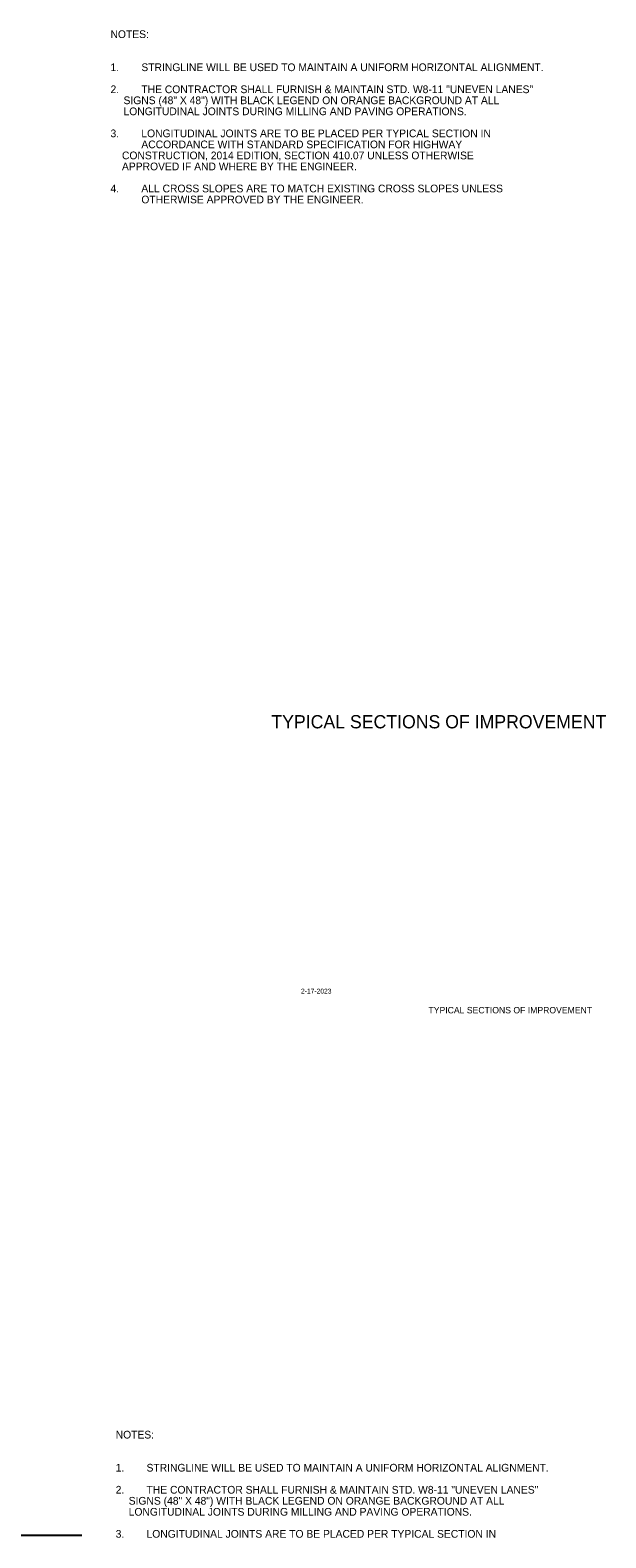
# Model space of a CAD drawing. Extents: x 549600 to 1930787, y -1955432 to 596640.
# Drawn here: x 552023 to 552546, y -1949917 to -1948549 of the extents above; entities that cross this region are included whole.
import ezdxf

# ---------------------------------------------------------------- set-up
doc = ezdxf.new("R2010")
doc.units = 0
for name, color, linetype in [('R_Border', 7, 'Continuous'), ('R_Border Notes', 7, 'Continuous'), ('R_Border Prem', 7, 'Continuous')]:
    doc.layers.add(name, color=color, linetype=linetype)

msp = doc.modelspace()

# ---------------------------------------------------------------- linework, layer by layer
at = {"layer": 'R_Border'}
msp.add_line((551009, -1949914), (552070.2, -1949914), dxfattribs=at)

# ---------------------------------------------------------------- texts
msp.add_text('TYPICAL SECTIONS OF IMPROVEMENT', height=12, rotation=360, dxfattribs=at).set_placement((552242.3, -1949182.1))
at = {"layer": 'R_Border Notes'}
for s, p in [('NOTES: ', (552096.3, -1948555.8)), ('1.', (552096.3, -1948585.8)), ('STRINGLINE WILL BE USED TO MAINTAIN A UNIFORM HORIZONTAL ALIGNMENT.', (552124.3, -1948585.8)), ('2.', (552096.3, -1948605.8)), ('THE CONTRACTOR SHALL FURNISH & MAINTAIN STD. W8-11 "UNEVEN LANES" ', (552124.3, -1948605.8)), ('    SIGNS (48" X 48") WITH BLACK LEGEND ON ORANGE BACKGROUND AT ALL ', (552097.7, -1948615.8)), ('    LONGITUDINAL JOINTS DURING MILLING AND PAVING OPERATIONS.', (552097.7, -1948625.8)), ('3.', (552096.3, -1948645.8)), ('LONGITUDINAL JOINTS ARE TO BE PLACED PER TYPICAL SECTION IN ', (552124.3, -1948645.8)), ('ACCORDANCE WITH STANDARD SPECIFICATION FOR HIGHWAY', (552124.3, -1948655.8)), ('    APPROVED IF AND WHERE BY THE ENGINEER.', (552096.3, -1948675.8)), ('    CONSTRUCTION, 2014 EDITION, SECTION 410.07 UNLESS OTHERWISE', (552096.3, -1948665.8)), ('4.', (552096.3, -1948695.8)), ('ALL CROSS SLOPES ARE TO MATCH EXISTING CROSS SLOPES UNLESS ', (552124.3, -1948695.8)), ('OTHERWISE APPROVED BY THE ENGINEER.', (552124.3, -1948705.8)), ('NOTES: ', (552101, -1949826.4)), ('1.', (552101, -1949856.4)), ('STRINGLINE WILL BE USED TO MAINTAIN A UNIFORM HORIZONTAL ALIGNMENT.', (552129, -1949856.4)), ('2.', (552101, -1949876.4)), ('THE CONTRACTOR SHALL FURNISH & MAINTAIN STD. W8-11 "UNEVEN LANES" ', (552129, -1949876.4)), ('    SIGNS (48" X 48") WITH BLACK LEGEND ON ORANGE BACKGROUND AT ALL ', (552102.4, -1949886.4)), ('    LONGITUDINAL JOINTS DURING MILLING AND PAVING OPERATIONS.', (552102.4, -1949896.4)), ('3.', (552101, -1949916.4)), ('LONGITUDINAL JOINTS ARE TO BE PLACED PER TYPICAL SECTION IN ', (552129, -1949916.4))]:
    msp.add_text(s, height=7, dxfattribs=at).set_placement(p)
at = {"layer": 'R_Border Prem'}
msp.add_text('2-17-2023', height=4.4, dxfattribs=at).set_placement((552269.2, -1949422.7))
msp.add_text('TYPICAL SECTIONS OF IMPROVEMENT', height=5.862, rotation=360, dxfattribs=at).set_placement((552384.9, -1949440.7))

doc.saveas('drawing.dxf')
